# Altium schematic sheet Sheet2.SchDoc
size A3; SheetNumber: 4; SheetTotal: 4
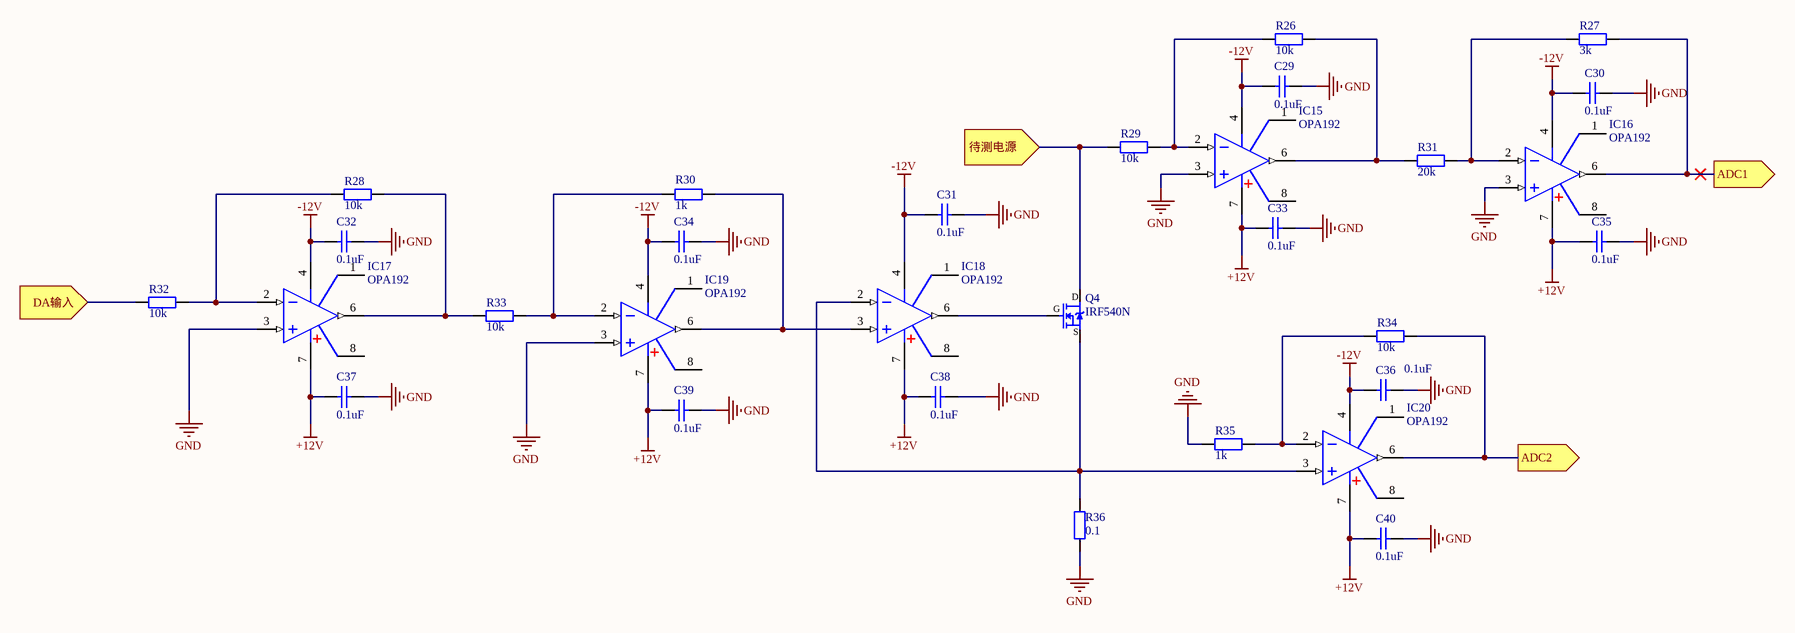
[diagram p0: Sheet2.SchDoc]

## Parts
C29  0.1uF  [瓷片电容]
C30  0.1uF  [瓷片电容]
C31  0.1uF  [瓷片电容]
C32  0.1uF  [瓷片电容]
C33  0.1uF  [瓷片电容]
C34  0.1uF  [瓷片电容]
C35  0.1uF  [瓷片电容]
C36  0.1uF  [瓷片电容]
C37  0.1uF  [瓷片电容]
C38  0.1uF  [瓷片电容]
C39  0.1uF  [瓷片电容]
C40  0.1uF  [瓷片电容]
IC15  OPA192  [SOP8_N]
IC16  OPA192  [SOP8_N]
IC17  OPA192  [SOP8_N]
IC18  OPA192  [SOP8_N]
IC19  OPA192  [SOP8_N]
IC20  OPA192  [SOP8_N]
Q4  IRF540N  [TO263-3B]
R26  10k  [RS 1/4W]
R27  3k  [RS 1/4W]
R28  10k  [RS 1/4W]
R29  10k  [RS 1/4W]
R30  1k  [RS 1/4W]
R31  20k  [RS 1/4W]
R32  10k  [RS 1/4W]
R33  10k  [RS 1/4W]
R34  10k  [RS 1/4W]
R35  1k  [RS 1/4W]
R36  0.1  [RS 1/4W]

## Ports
ADC1 (out), ADC2 (out), DA输入 (in), 待测电源 (in)

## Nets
+12V: C33.1 C35.1 C37.1 C38.1 C39.1 C40.1 IC15.7(V+) IC16.7(V+) IC17.7(V+) IC18.7(V+) IC19.7(V+) IC20.7(V+)
-12V: C29.1 C30.1 C31.1 C32.1 C34.1 C36.1 IC15.4(V-) IC16.4(V-) IC17.4(V-) IC18.4(V-) IC19.4(V-) IC20.4(V-)
GND: C29.2 C30.2 C31.2 C32.2 C33.2 C34.2 C35.2 C36.2 C37.2 C38.2 C39.2 C40.2 IC15.3(IN+) IC16.3(IN+) IC17.3(IN+) IC19.3(IN+) R35.1 R36.1
ADC1: IC16.6(OUT) R27.2 ; port ADC1
ADC2: IC20.6(OUT) R34.2 ; port ADC2
DA输入: R32.1 ; port DA输入
待测电源: Q4.2(S) R29.1 ; port 待测电源
NetIC15_2: IC15.2(IN-) R26.1 R29.2
NetIC15_6: IC15.6(OUT) R26.2 R31.1
NetIC16_2: IC16.2(IN-) R27.1 R31.2
NetIC17_2: IC17.2(IN-) R28.1 R32.2
NetIC17_6: IC17.6(OUT) R28.2 R33.1
NetIC18_2: IC18.2(IN-) IC20.3(IN+) Q4.3(D) R36.2
NetIC18_3: IC18.3(IN+) IC19.6(OUT) R30.2
NetIC18_6: IC18.6(OUT) Q4.1(G)
NetIC19_2: IC19.2(IN-) R30.1 R33.2
NetIC20_2: IC20.2(IN-) R34.1 R35.2

Not connected (* = marked no-connect by the designer): IC15 1 8; IC16 1 8; IC17 1 8; IC18 1 8; IC19 1 8; IC20 1 8

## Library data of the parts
C29-C40 = Cap_DIP: 直插电容; Value: 100nF; Voltage: 63V
IC15-IC20 = OPA192: High-Voltage, Rail-to-Rail Input/Output, 5µV, 0.2µV/˚C, Precision Operational Amplifier; BOM名称: 单路精密运放; 版权归属: 源创客
Q4 = IRF540N: N沟场 100V/22A; BOM名称: 效应管; 版权归属: 源创客
R26-R36 = Res_DIP: 直插电阻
